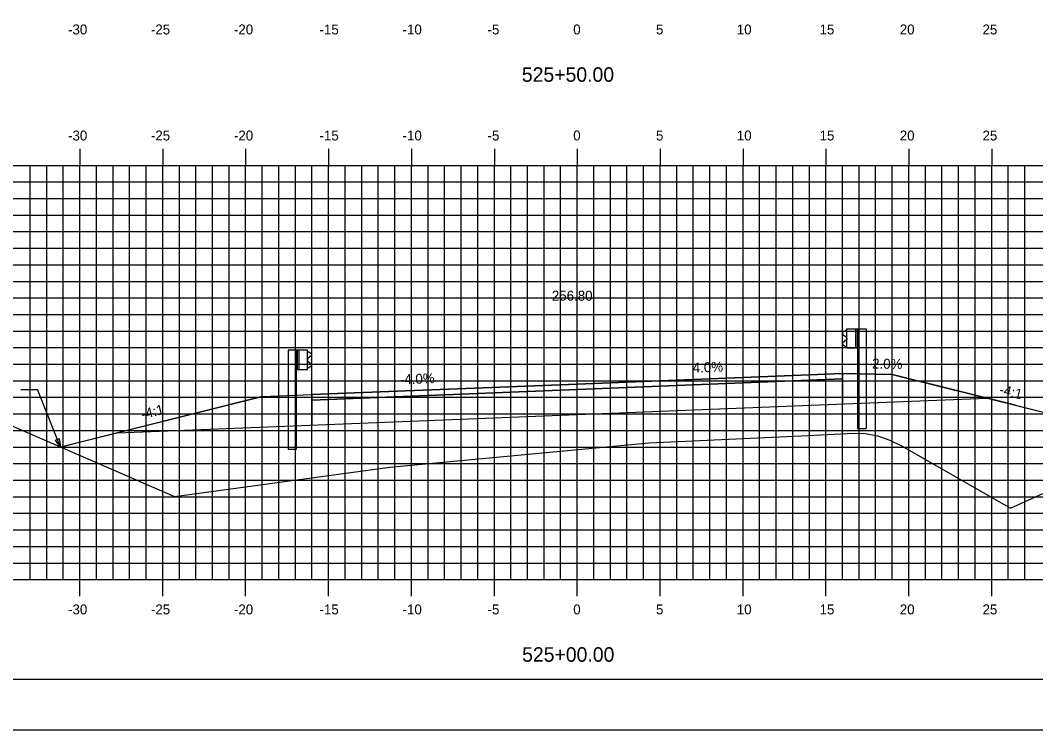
# Model space of a CAD drawing. Extents: x 1170543 to 1177585, y 609599 to 610623.
# Drawn here: x 1175545.2 to 1175606.5, y 609598.8 to 609641.6 of the extents above; entities that cross this region are included whole.
import ezdxf

# ---------------------------------------------------------------- set-up
doc = ezdxf.new("R2010")
doc.units = 0
for name, color, linetype in [('ANNOTATION', 7, 'Continuous'), ('BORDER', 7, 'Continuous'), ('D_Guardrail_Beam_Lt', 7, 'Continuous'), ('D_Guardrail_Beam_Rt', 7, 'Continuous'), ('D_Roadway_Centerline', 7, 'Continuous'), ('D_Roadway_Centerline_Text', 7, 'Continuous'), ('D_Roadway_Edge_Shoulder', 7, 'Continuous'), ('D_Roadway_Edge_TW', 7, 'Continuous'), ('D_Roadway_Pavement', 7, 'Continuous'), ('D_Roadway_SlopeLines', 7, 'Continuous'), ('D_Roadway_SubGrade', 7, 'Continuous'), ('H_V ANNOTATION', 7, 'Continuous'), ('MAJOR', 7, 'Continuous'), ('MINOR', 7, 'Continuous'), ('PLOT BOUNDARY', 7, 'Continuous'), ('S_Roadway_Centerline', 7, 'Continuous'), ('SHADING', 7, 'Continuous')]:
    doc.layers.add(name, color=color, linetype=linetype)

msp = doc.modelspace()

# ---------------------------------------------------------------- linework, layer by layer
at = {"layer": 'ANNOTATION'}
for p in [(1175545.264, 609619.349), (1175547.655, 609615.872)]:
    msp.add_line(p, (1175546.264, 609619.349), dxfattribs=at)
msp.add_lwpolyline([(1175547.585, 609616.383), (1175547.655, 609615.872), (1175547.353, 609616.29)], close=True, dxfattribs=at)
at = {"layer": 'BORDER'}
msp.add_line((1175503.826, 609601.872), (1175663.826, 609601.872), dxfattribs=at)
at = {"layer": 'D_Guardrail_Beam_Lt'}
for p, q in [((1175561.392, 609621.719), (1175561.392, 609615.719)), ((1175561.863, 609621.719), (1175561.392, 609621.719)), ((1175562.55, 609621.719), (1175561.863, 609621.719)), ((1175561.863, 609621.719), (1175561.863, 609620.553)), ((1175561.925, 609621.719), (1175561.925, 609620.553)), ((1175562.029, 609621.719), (1175562.029, 609620.553)), ((1175562.55, 609620.553), (1175562.55, 609621.719)), ((1175562.55, 609621.636), (1175562.624, 609621.621)), ((1175562.64, 609621.615), (1175562.783, 609621.515)), ((1175562.554, 609621.171), (1175562.554, 609621.101)), ((1175562.783, 609621.372), (1175562.588, 609621.236)), ((1175562.588, 609621.037), (1175562.783, 609620.9)), ((1175561.863, 609620.553), (1175562.55, 609620.553)), ((1175561.883, 609615.719), (1175561.883, 609620.553)), ((1175562.624, 609620.651), (1175562.55, 609620.636)), ((1175562.783, 609620.757), (1175562.64, 609620.657)), ((1175561.883, 609615.719), (1175561.392, 609615.719))]:
    msp.add_line(p, q, dxfattribs=at)
for centre, major_axis, start_param, end_param in [((1175562.616, 609621.581), (0.0417, 0), 0.959931, 1.376053), ((1175562.733, 609621.443), (0.0877, 0), 5.323254, 7.243116), ((1175562.633, 609621.171), (-0.0789, 0), 5.323254, 6.283185), ((1175562.633, 609621.101), (-0.0789, 0), 6.283185, 7.243116), ((1175562.733, 609620.829), (0.0877, 0), 5.323254, 7.243116), ((1175562.616, 609620.691), (0.0417, 0), 4.907132, 5.323254)]:
    msp.add_ellipse(centre, major_axis=major_axis, ratio=0.995501, start_param=start_param, end_param=end_param, dxfattribs=at)
at = {"layer": 'D_Guardrail_Beam_Rt'}
for p, q in [((1175595.002, 609622.895), (1175594.858, 609622.795)), ((1175595.092, 609622.916), (1175595.017, 609622.901)), ((1175595.092, 609622.999), (1175595.779, 609622.999)), ((1175595.092, 609621.833), (1175595.092, 609622.999)), ((1175595.612, 609622.999), (1175595.612, 609621.833)), ((1175595.717, 609622.999), (1175595.717, 609621.833)), ((1175595.779, 609622.999), (1175596.25, 609622.999)), ((1175595.779, 609622.999), (1175595.779, 609621.833)), ((1175596.25, 609622.999), (1175596.25, 609616.999)), ((1175594.858, 609622.652), (1175595.054, 609622.516)), ((1175595.054, 609622.317), (1175594.858, 609622.18)), ((1175595.087, 609622.451), (1175595.087, 609622.381)), ((1175594.858, 609622.037), (1175595.002, 609621.937)), ((1175595.017, 609621.931), (1175595.092, 609621.916)), ((1175595.779, 609621.833), (1175595.092, 609621.833)), ((1175595.758, 609616.999), (1175595.758, 609621.833)), ((1175595.758, 609616.999), (1175596.25, 609616.999))]:
    msp.add_line(p, q, dxfattribs=at)
for centre, major_axis, start_param, end_param in [((1175594.908, 609622.723), (-0.0877, 0), 5.323254, 7.243116), ((1175595.026, 609622.861), (-0.0417, 0), 4.907132, 5.323254), ((1175594.908, 609622.109), (-0.0877, 0), 5.323254, 7.243116), ((1175595.008, 609622.451), (0.0789, 0), 0, 0.959931), ((1175595.008, 609622.381), (0.0789, 0), 5.323254, 6.283185), ((1175595.026, 609621.971), (-0.0417, 0), 0.959931, 1.376053)]:
    msp.add_ellipse(centre, major_axis=major_axis, ratio=0.995501, start_param=start_param, end_param=end_param, dxfattribs=at)
at = {"layer": 'D_Roadway_Centerline'}
msp.add_lwpolyline([(1175547.655, 609615.872), (1175548.715, 609616.137), (1175559.826, 609618.915), (1175562.826, 609619.035), (1175578.826, 609619.675), (1175594.826, 609620.315), (1175597.826, 609620.255), (1175605.251, 609618.399), (1175611.458, 609616.847)], dxfattribs=at)
at = {"layer": 'D_Roadway_Edge_Shoulder'}
for points in [[(1175594.826, 609620.315), (1175594.826, 609619.982)], [(1175562.826, 609619.035), (1175562.826, 609618.702)]]:
    msp.add_lwpolyline(points, dxfattribs=at)
at = {"layer": 'D_Roadway_Edge_TW'}
msp.add_lwpolyline([(1175594.826, 609619.982), (1175594.826, 609620.315), (1175578.826, 609619.675), (1175562.826, 609619.035), (1175562.826, 609618.702), (1175578.826, 609619.342)], close=True, dxfattribs=at)
at = {"layer": 'D_Roadway_Pavement'}
msp.add_lwpolyline([(1175594.826, 609619.982), (1175594.826, 609619.982), (1175578.826, 609619.342), (1175562.826, 609618.702), (1175562.826, 609618.702), (1175578.826, 609619.342)], close=True, dxfattribs=at)
for points in [[(1175594.826, 609619.982), (1175594.826, 609619.982)], [(1175594.826, 609619.982), (1175594.826, 609619.982)], [(1175562.826, 609618.702), (1175562.826, 609618.702)], [(1175562.826, 609618.702), (1175562.826, 609618.702)]]:
    msp.add_lwpolyline(points, dxfattribs=at)
at = {"layer": 'D_Roadway_SlopeLines'}
for points in [[(1175597.826, 609620.255), (1175613.629, 609616.304)], [(1175559.826, 609618.915), (1175547.655, 609615.872)]]:
    msp.add_lwpolyline(points, dxfattribs=at)
at = {"layer": 'D_Roadway_SubGrade'}
for p, q in [((1175597.826, 609620.255), (1175594.826, 609620.315)), ((1175594.826, 609620.315), (1175594.826, 609618.482)), ((1175605.251, 609618.399), (1175597.826, 609620.255)), ((1175594.826, 609619.982), (1175578.826, 609619.342)), ((1175594.826, 609618.482), (1175594.826, 609619.982)), ((1175559.826, 609618.915), (1175562.826, 609619.035)), ((1175578.826, 609619.342), (1175562.826, 609618.702)), ((1175562.826, 609619.035), (1175562.826, 609617.202)), ((1175548.715, 609616.137), (1175559.826, 609618.915)), ((1175562.826, 609618.702), (1175562.826, 609617.202))]:
    msp.add_line(p, q, dxfattribs=at)
at = {"layer": 'MAJOR'}
for p, q in [((1175548.826, 609633.874), (1175548.826, 609632.872)), ((1175553.826, 609633.874), (1175553.826, 609632.872)), ((1175558.826, 609633.874), (1175558.826, 609632.872)), ((1175563.826, 609633.874), (1175563.826, 609632.872)), ((1175568.826, 609633.874), (1175568.826, 609632.872)), ((1175573.826, 609633.874), (1175573.826, 609632.872)), ((1175578.826, 609633.874), (1175578.826, 609632.872)), ((1175583.826, 609633.874), (1175583.826, 609632.872)), ((1175588.826, 609633.874), (1175588.826, 609632.872)), ((1175593.826, 609633.874), (1175593.826, 609632.872)), ((1175598.826, 609633.874), (1175598.826, 609632.872)), ((1175603.826, 609633.874), (1175603.826, 609632.872)), ((1175508.826, 609632.872), (1175648.826, 609632.872)), ((1175508.826, 609632.872), (1175648.826, 609632.872)), ((1175548.826, 609607.872), (1175548.826, 609632.872)), ((1175553.826, 609607.872), (1175553.826, 609632.872)), ((1175558.826, 609607.872), (1175558.826, 609632.872)), ((1175563.826, 609607.872), (1175563.826, 609632.872)), ((1175568.826, 609607.872), (1175568.826, 609632.872)), ((1175573.826, 609607.872), (1175573.826, 609632.872)), ((1175578.826, 609607.872), (1175578.826, 609632.872)), ((1175583.826, 609607.872), (1175583.826, 609632.872)), ((1175588.826, 609607.872), (1175588.826, 609632.872)), ((1175593.826, 609607.872), (1175593.826, 609632.872)), ((1175598.826, 609607.872), (1175598.826, 609632.872)), ((1175603.826, 609607.872), (1175603.826, 609632.872)), ((1175508.826, 609627.872), (1175648.826, 609627.872)), ((1175508.826, 609622.872), (1175648.826, 609622.872)), ((1175508.826, 609617.872), (1175648.826, 609617.872)), ((1175508.826, 609612.872), (1175648.826, 609612.872)), ((1175508.826, 609607.872), (1175648.826, 609607.872)), ((1175508.826, 609607.872), (1175648.826, 609607.872)), ((1175548.826, 609606.87), (1175548.826, 609607.872)), ((1175553.826, 609606.87), (1175553.826, 609607.872)), ((1175558.826, 609606.87), (1175558.826, 609607.872)), ((1175563.826, 609606.87), (1175563.826, 609607.872)), ((1175568.826, 609606.87), (1175568.826, 609607.872)), ((1175573.826, 609606.87), (1175573.826, 609607.872)), ((1175578.826, 609606.87), (1175578.826, 609607.872)), ((1175583.826, 609606.87), (1175583.826, 609607.872)), ((1175588.826, 609606.87), (1175588.826, 609607.872)), ((1175593.826, 609606.87), (1175593.826, 609607.872)), ((1175598.826, 609606.87), (1175598.826, 609607.872)), ((1175603.826, 609606.87), (1175603.826, 609607.872))]:
    msp.add_line(p, q, dxfattribs=at)
at = {"layer": 'MINOR'}
for p, q in [((1175545.826, 609607.872), (1175545.826, 609632.872)), ((1175546.826, 609607.872), (1175546.826, 609632.872)), ((1175547.826, 609607.872), (1175547.826, 609632.872)), ((1175549.826, 609607.872), (1175549.826, 609632.872)), ((1175550.826, 609607.872), (1175550.826, 609632.872)), ((1175551.826, 609607.872), (1175551.826, 609632.872)), ((1175552.826, 609607.872), (1175552.826, 609632.872)), ((1175554.826, 609607.872), (1175554.826, 609632.872)), ((1175555.826, 609607.872), (1175555.826, 609632.872)), ((1175556.826, 609607.872), (1175556.826, 609632.872)), ((1175557.826, 609607.872), (1175557.826, 609632.872)), ((1175559.826, 609607.872), (1175559.826, 609632.872)), ((1175560.826, 609607.872), (1175560.826, 609632.872)), ((1175561.826, 609607.872), (1175561.826, 609632.872)), ((1175562.826, 609607.872), (1175562.826, 609632.872)), ((1175564.826, 609607.872), (1175564.826, 609632.872)), ((1175565.826, 609607.872), (1175565.826, 609632.872)), ((1175566.826, 609607.872), (1175566.826, 609632.872)), ((1175567.826, 609607.872), (1175567.826, 609632.872)), ((1175569.826, 609607.872), (1175569.826, 609632.872)), ((1175570.826, 609607.872), (1175570.826, 609632.872)), ((1175571.826, 609607.872), (1175571.826, 609632.872)), ((1175572.826, 609607.872), (1175572.826, 609632.872)), ((1175574.826, 609607.872), (1175574.826, 609632.872)), ((1175575.826, 609607.872), (1175575.826, 609632.872)), ((1175576.826, 609607.872), (1175576.826, 609632.872)), ((1175577.826, 609607.872), (1175577.826, 609632.872)), ((1175579.826, 609607.872), (1175579.826, 609632.872)), ((1175580.826, 609607.872), (1175580.826, 609632.872)), ((1175581.826, 609607.872), (1175581.826, 609632.872)), ((1175582.826, 609607.872), (1175582.826, 609632.872)), ((1175584.826, 609607.872), (1175584.826, 609632.872)), ((1175585.826, 609607.872), (1175585.826, 609632.872)), ((1175586.826, 609607.872), (1175586.826, 609632.872)), ((1175587.826, 609607.872), (1175587.826, 609632.872)), ((1175589.826, 609607.872), (1175589.826, 609632.872)), ((1175590.826, 609607.872), (1175590.826, 609632.872)), ((1175591.826, 609607.872), (1175591.826, 609632.872)), ((1175592.826, 609607.872), (1175592.826, 609632.872)), ((1175594.826, 609607.872), (1175594.826, 609632.872)), ((1175595.826, 609607.872), (1175595.826, 609632.872)), ((1175596.826, 609607.872), (1175596.826, 609632.872)), ((1175597.826, 609607.872), (1175597.826, 609632.872)), ((1175599.826, 609607.872), (1175599.826, 609632.872)), ((1175600.826, 609607.872), (1175600.826, 609632.872)), ((1175601.826, 609607.872), (1175601.826, 609632.872)), ((1175602.826, 609607.872), (1175602.826, 609632.872)), ((1175604.826, 609607.872), (1175604.826, 609632.872)), ((1175605.826, 609607.872), (1175605.826, 609632.872)), ((1175508.826, 609631.872), (1175648.826, 609631.872)), ((1175508.826, 609630.872), (1175648.826, 609630.872)), ((1175508.826, 609629.872), (1175648.826, 609629.872)), ((1175508.826, 609628.872), (1175648.826, 609628.872)), ((1175508.826, 609626.872), (1175648.826, 609626.872)), ((1175508.826, 609625.872), (1175648.826, 609625.872)), ((1175508.826, 609624.872), (1175648.826, 609624.872)), ((1175508.826, 609623.872), (1175648.826, 609623.872)), ((1175508.826, 609621.872), (1175648.826, 609621.872)), ((1175508.826, 609620.872), (1175648.826, 609620.872)), ((1175508.826, 609619.872), (1175648.826, 609619.872)), ((1175508.826, 609618.872), (1175648.826, 609618.872)), ((1175508.826, 609616.872), (1175648.826, 609616.872)), ((1175508.826, 609615.872), (1175648.826, 609615.872)), ((1175508.826, 609614.872), (1175648.826, 609614.872)), ((1175508.826, 609613.872), (1175648.826, 609613.872)), ((1175508.826, 609611.872), (1175648.826, 609611.872)), ((1175508.826, 609610.872), (1175648.826, 609610.872)), ((1175508.826, 609609.872), (1175648.826, 609609.872)), ((1175508.826, 609608.872), (1175648.826, 609608.872))]:
    msp.add_line(p, q, dxfattribs=at)
at = {"layer": 'PLOT BOUNDARY'}
msp.add_lwpolyline([(1175495.733, 609598.813), (1175665.733, 609598.813), (1175665.733, 609708.813), (1175495.733, 609708.813)], close=True, dxfattribs=at)
at = {"layer": 'S_Roadway_Centerline'}
msp.add_lwpolyline([(1175508.826, 609626.466), (1175510.181, 609626.434), (1175512.593, 609626.377), (1175514.592, 609626.323), (1175517.646, 609626.242), (1175522.038, 609626.067), (1175522.36, 609626.054), (1175522.41, 609626.04), (1175523.584, 609625.687), (1175525.526, 609625.19), (1175534.027, 609621.8), (1175554.529, 609612.882), (1175567.513, 609614.665), (1175583.156, 609616.122), (1175592.325, 609616.553), (1175595.518, 609616.703), (1175596.219, 609616.68), (1175596.937, 609616.544), (1175597.674, 609616.291), (1175598.43, 609615.915), (1175604.964, 609612.174), (1175606.918, 609613.062)], dxfattribs=at)
at = {"layer": 'SHADING'}
msp.add_line((1175551.096, 609616.733), (1175603.527, 609618.83), dxfattribs=at)

# ---------------------------------------------------------------- texts
at = {"layer": 'ANNOTATION'}
for s, rotation, p in [('4.0%', 2.29061, (1175585.802, 609620.355)), ('-2.0%', 358.85424, (1175596.339, 609620.619)), ('-4.0%', 2.29061, (1175568.142, 609619.648)), ('-4:1', 345.96376, (1175604.239, 609619.083)), ('-4:1', 14.03624, (1175552.603, 609617.54))]:
    msp.add_text(s, height=0.6, rotation=rotation, dxfattribs=at).set_placement(p)
at = {"layer": 'D_Roadway_Centerline'}
for s, p in [('C', (1175578.821, 609619.675)), ('L', (1175578.826, 609619.668))]:
    msp.add_text(s, height=0.0146, dxfattribs=at).set_placement(p)
at = {"layer": 'D_Roadway_Centerline_Text'}
msp.add_text('256.80', height=0.6, dxfattribs=at).set_placement((1175577.296, 609624.707))
at = {"layer": 'H_V ANNOTATION'}
for s, height, p in [('-30', 0.6, (1175548.114, 609640.772)), ('-25', 0.6, (1175553.112, 609640.772)), ('-20', 0.6, (1175558.12, 609640.772)), ('-15', 0.6, (1175563.283, 609640.772)), ('-10', 0.6, (1175568.291, 609640.772)), ('-5', 0.6, (1175573.417, 609640.772)), ('0', 0.6, (1175578.585, 609640.772)), ('5', 0.6, (1175583.577, 609640.772)), ('10', 0.6, (1175588.451, 609640.772)), ('15', 0.6, (1175593.443, 609640.772)), ('20', 0.6, (1175598.28, 609640.772)), ('25', 0.6, (1175603.272, 609640.772)), ('525+50.00', 0.875, (1175575.486, 609637.915)), ('-30', 0.6, (1175548.114, 609634.372)), ('-25', 0.6, (1175553.112, 609634.372)), ('-20', 0.6, (1175558.12, 609634.372)), ('-15', 0.6, (1175563.283, 609634.372)), ('-10', 0.6, (1175568.291, 609634.372)), ('-5', 0.6, (1175573.417, 609634.372)), ('0', 0.6, (1175578.585, 609634.372)), ('5', 0.6, (1175583.577, 609634.372)), ('10', 0.6, (1175588.451, 609634.372)), ('15', 0.6, (1175593.443, 609634.372)), ('20', 0.6, (1175598.28, 609634.372)), ('25', 0.6, (1175603.272, 609634.372)), ('-30', 0.6, (1175548.114, 609605.772)), ('-25', 0.6, (1175553.112, 609605.772)), ('-20', 0.6, (1175558.12, 609605.772)), ('-15', 0.6, (1175563.283, 609605.772)), ('-10', 0.6, (1175568.291, 609605.772)), ('-5', 0.6, (1175573.417, 609605.772)), ('0', 0.6, (1175578.585, 609605.772)), ('5', 0.6, (1175583.577, 609605.772)), ('10', 0.6, (1175588.451, 609605.772)), ('15', 0.6, (1175593.443, 609605.772)), ('20', 0.6, (1175598.28, 609605.772)), ('25', 0.6, (1175603.272, 609605.772)), ('525+00.00', 0.875, (1175575.502, 609602.915))]:
    msp.add_text(s, height=height, dxfattribs=at).set_placement(p)

doc.saveas('drawing.dxf')
